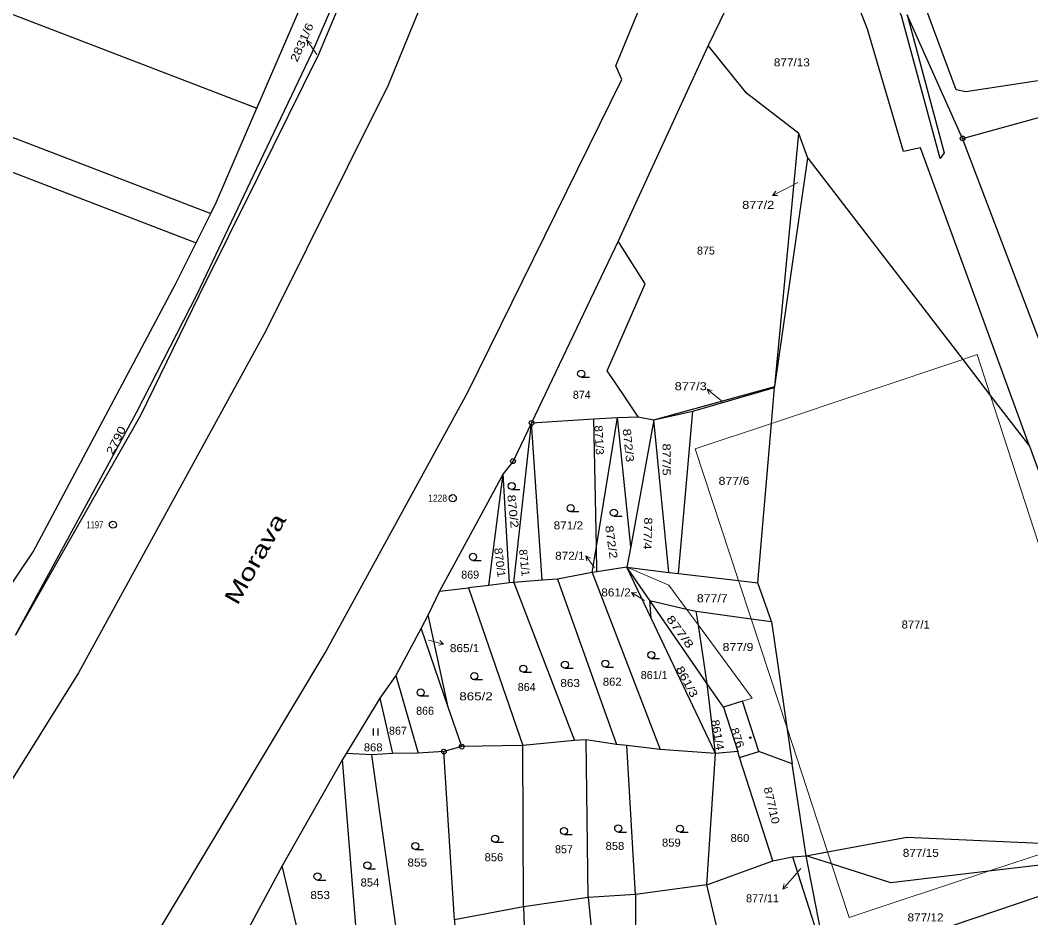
# Model space of a CAD drawing. Extents: x -546984 to -546090, y -1194931 to -1194069.
# Drawn here: x -546479.3 to -546264.7, y -1194458.7 to -1194268.1 of the extents above; entities that cross this region are included whole.
import ezdxf
from ezdxf.enums import TextEntityAlignment as Align

# ---------------------------------------------------------------- set-up
doc = ezdxf.new("R2010")
doc.units = 0
doc.header["$LTSCALE"] = 0.68
for name, color, linetype, lineweight in [('1', 7, 'Continuous', 25), ('3', 7, 'Continuous', 25), ('4', 7, 'Continuous', 13), ('5', 7, 'Continuous', 25), ('7', 7, 'Continuous', 13), ('8', 7, 'Continuous', 25)]:
    doc.layers.add(name, color=color, linetype=linetype, lineweight=lineweight)
doc.layers.add('2', color=7, linetype='Continuous')

msp = doc.modelspace()

# ---------------------------------------------------------------- linework, layer by layer
at = {"layer": '1'}
for p, q in [((-546321.44, -1194249.16), (-546333.19, -1194273.39)), ((-546535.728, -1194271.832), (-546438.82, -1194309.09)), ((-546319.09, -1194345.84), (-546313.93, -1194292.13)), ((-546352.31, -1194314.99), (-546370.72, -1194353.57)), ((-546356.95, -1194379.79), (-546352.43, -1194352.43)), ((-546352.43, -1194352.43), (-546348.07, -1194352.27)), ((-546349.66, -1194379.83), (-546352.43, -1194352.43)), ((-546344.72, -1194352.94), (-546336.5, -1194351.06)), ((-546339.49, -1194385.58), (-546336.5, -1194351.06)), ((-546374.51, -1194387.45), (-546370.72, -1194353.57)), ((-546368.49, -1194387), (-546370.72, -1194353.57)), ((-546264.98, -1194358.54), (-546233.72, -1194444.1)), ((-546379.81, -1194388.1), (-546376.75, -1194364.41)), ((-546375.42, -1194387.56), (-546376.75, -1194364.41)), ((-546356.84, -1194385.21), (-546356.95, -1194379.79)), ((-546345.58, -1194391.31), (-546350.47, -1194384.21)), ((-546357.87, -1194385.37), (-546343.43, -1194422.95)), ((-546341.57, -1194385.33), (-546339.49, -1194385.58)), ((-546390.24, -1194389.34), (-546384.07, -1194388.61)), ((-546384.07, -1194388.61), (-546372.53, -1194422.11)), ((-546319.8, -1194395.78), (-546322.7, -1194387.52)), ((-546390.24, -1194389.34), (-546392.7, -1194394.32)), ((-546345.33, -1194395.05), (-546345.58, -1194391.31)), ((-546392.7, -1194394.32), (-546394.12, -1194397.19)), ((-546388.4, -1194413.93), (-546392.7, -1194394.32)), ((-546399.52, -1194407.25), (-546394.82, -1194423.7)), ((-546329.98, -1194413.96), (-546333.39, -1194409.02)), ((-546402.96, -1194412.02), (-546400.26, -1194423.75)), ((-546361.61, -1194421.01), (-546372.53, -1194422.11)), ((-546352.67, -1194421.88), (-546359.11, -1194420.91)), ((-546372.44, -1194456.33), (-546372.53, -1194422.11)), ((-546326.53, -1194424.65), (-546322.48, -1194423.34)), ((-546410.85, -1194425.09), (-546423.69, -1194447.64)), ((-546410.09, -1194423.81), (-546410.85, -1194425.09)), ((-546407.84, -1194462.95), (-546410.85, -1194425.09)), ((-546387.04, -1194459.12), (-546389.33, -1194423.37)), ((-546333.5, -1194451.68), (-546331.69, -1194423.79)), ((-546326.94, -1194423.37), (-546331.69, -1194423.79)), ((-546423.69, -1194447.64), (-546434.68, -1194468.08)), ((-546419.49, -1194465.08), (-546423.69, -1194447.64))]:
    msp.add_line(p, q, dxfattribs=at)
for points in [[(-546389.24, -1194211.62), (-546383.21, -1194213.85), (-546381.43, -1194214.52), (-546374.55, -1194220.96), (-546389.16, -1194255.29), (-546392.45, -1194260.52), (-546401.16, -1194281.84), (-546427.1, -1194334), (-546466.91, -1194406.62), (-546525.73, -1194500.91), (-546575.37, -1194569.17), (-546611.42, -1194614.13), (-546654.08, -1194661.28), (-546675.45, -1194680.69), (-546700.89, -1194697.8)], [(-546480.28, -1194398.62), (-546454.62, -1194351.38), (-546441.74, -1194326.26), (-546429.78, -1194301.03), (-546417.24, -1194274.74), (-546406, -1194248.75), (-546398.33, -1194228.83), (-546392.14, -1194217.18)], [(-546392.14, -1194217.18), (-546393.03, -1194219.38), (-546404.99, -1194249.12), (-546415.92, -1194275.33), (-546428.91, -1194301.5), (-546441.35, -1194326.56), (-546453.74, -1194351.98), (-546480.28, -1194398.62)], [(-546653.83, -1194720.11), (-546626.66, -1194696.55), (-546572.27, -1194633.02), (-546541.58, -1194595.62), (-546489.43, -1194522.46), (-546452.3, -1194465.52), (-546414.56, -1194402.38), (-546384.23, -1194347.08), (-546351.57, -1194280.62), (-546352.84, -1194277.72), (-546335.99, -1194236.72), (-546326.04, -1194236.79), (-546324.23, -1194237.51), (-546321.88, -1194231.5)], [(-546290.97, -1194266.91), (-546283.11, -1194296.25), (-546283.98, -1194297.43), (-546292.16, -1194267.14), (-546301.17, -1194245.95), (-546309.75, -1194237.15), (-546316.69, -1194232.35)], [(-546223.97, -1194273.81), (-546237.14, -1194276.93), (-546278.51, -1194283.23), (-546280.55, -1194282.82), (-546289.26, -1194259.3), (-546295.56, -1194244.05), (-546298.03, -1194240.43)], [(-546264.98, -1194358.54), (-546288.15, -1194295.14), (-546291.74, -1194295.93), (-546299.4, -1194269.93), (-546306.67, -1194251.25), (-546318.22, -1194242.52)], [(-546518.881, -1194252.193), (-546429.01, -1194286.74), (-546419.67, -1194265.11)], [(-546239.33, -1194397.92), (-546258.87, -1194346.57), (-546279.19, -1194293.17), (-546290.97, -1194266.91)], [(-546537.003, -1194273.318), (-546538.28, -1194278.28), (-546441.91, -1194315.32), (-546438.82, -1194309.09)], [(-546333.19, -1194273.39), (-546333.64, -1194274.33), (-546352.31, -1194314.99)], [(-546313.93, -1194292.13), (-546325.1, -1194283.56), (-546333.19, -1194273.39)], [(-546279.19, -1194293.17), (-546239.15, -1194282.15), (-546214.13, -1194275.26)], [(-546438.82, -1194309.09), (-546437.6, -1194306.64), (-546429.01, -1194286.74)], [(-546319.09, -1194345.84), (-546312.06, -1194297.34), (-546313.93, -1194292.13)], [(-546312.06, -1194297.34), (-546279.16, -1194340.1), (-546273.25, -1194347.79), (-546264.98, -1194358.54)], [(-546566.87, -1194389.76), (-546564.43, -1194388.89), (-546559.37, -1194387.86), (-546556.14, -1194387.71), (-546553.09, -1194388.04), (-546526.4, -1194394.07), (-546501.89, -1194394.85), (-546489.42, -1194394.32), (-546486.31, -1194393.34), (-546483.36, -1194391.08), (-546476.54, -1194380.93), (-546446.29, -1194324.14), (-546441.91, -1194315.32)], [(-546348.07, -1194352.27), (-546350.47, -1194348.7), (-546353.12, -1194344.75), (-546354.63, -1194342.5), (-546346.62, -1194324.07), (-546352.31, -1194314.99)], [(-546348.07, -1194352.27), (-546344.72, -1194352.94), (-546319.09, -1194345.84)], [(-546336.5, -1194351.06), (-546319.15, -1194346.03), (-546319.09, -1194345.84)], [(-546322.7, -1194387.52), (-546319.8, -1194353.68), (-546319.15, -1194346.03)], [(-546370.72, -1194353.57), (-546357.47, -1194352.74), (-546352.43, -1194352.43)], [(-546370.72, -1194353.57), (-546374.65, -1194361.7), (-546376.75, -1194364.41)], [(-546357.87, -1194385.37), (-546356.95, -1194379.79), (-546357.47, -1194352.74)], [(-546376.75, -1194364.41), (-546382.42, -1194374.85), (-546390.24, -1194389.34)], [(-546331.69, -1194423.79), (-546345.33, -1194395.05), (-546350.47, -1194384.21), (-546356.84, -1194385.21), (-546357.87, -1194385.37)], [(-546365.22, -1194386.75), (-546368.49, -1194387), (-546374.51, -1194387.45), (-546361.61, -1194421.01)], [(-546357.87, -1194385.37), (-546365.22, -1194386.75), (-546352.67, -1194421.88)], [(-546339.49, -1194385.58), (-546326.76, -1194387.05), (-546322.7, -1194387.52)], [(-546374.51, -1194387.45), (-546375.42, -1194387.56), (-546379.81, -1194388.1), (-546384.07, -1194388.61)], [(-546331.69, -1194423.79), (-546333.39, -1194409.02), (-546345.58, -1194391.31)], [(-546345.58, -1194391.31), (-546337.83, -1194393.1), (-546335.75, -1194393.58)], [(-546333.39, -1194409.02), (-546335.3, -1194396.53), (-546335.75, -1194393.58)], [(-546335.75, -1194393.58), (-546324.09, -1194395.19), (-546319.8, -1194395.78)], [(-546394.12, -1194397.19), (-546399.52, -1194407.25), (-546402.96, -1194412.02), (-546410.09, -1194423.81)], [(-546385.53, -1194422.33), (-546388.4, -1194413.93), (-546394.12, -1194397.19)], [(-546319.8, -1194395.78), (-546316.54, -1194418.2), (-546315.41, -1194425.96)], [(-546322.48, -1194423.34), (-546325.94, -1194412.65), (-546329.98, -1194413.96), (-546326.94, -1194423.37)], [(-546358.67, -1194454.37), (-546359.11, -1194420.91), (-546361.61, -1194421.01)], [(-546372.53, -1194422.11), (-546385.53, -1194422.33), (-546389.33, -1194423.37)], [(-546348.67, -1194453.74), (-546350.47, -1194422.06), (-546352.67, -1194421.88)], [(-546331.69, -1194423.79), (-546343.43, -1194422.95), (-546350.47, -1194422.06)], [(-546319.48, -1194446.55), (-546315.32, -1194445.7), (-546312.37, -1194445.5), (-546315.41, -1194425.96), (-546322.48, -1194423.34)], [(-546399.41, -1194461.39), (-546404.6, -1194424.09), (-546410.09, -1194423.81)], [(-546389.33, -1194423.37), (-546394.82, -1194423.7), (-546400.26, -1194423.75), (-546404.6, -1194424.09)], [(-546333.5, -1194451.68), (-546319.48, -1194446.55), (-546326.53, -1194424.65), (-546326.94, -1194423.37)], [(-546312.37, -1194445.5), (-546307.85, -1194444.66), (-546291.01, -1194441.53), (-546256.43, -1194443.08), (-546233.72, -1194444.1)], [(-546233.72, -1194444.1), (-546273.66, -1194448.8), (-546294.44, -1194451.24), (-546307.01, -1194447.22), (-546312.37, -1194445.5)], [(-546307.77, -1194469.14), (-546299.75, -1194466.54), (-546235.74, -1194444.89), (-546233.72, -1194444.1)], [(-546315.32, -1194445.7), (-546307.77, -1194469.14), (-546312.37, -1194445.5)], [(-546323.11, -1194495.59), (-546333.5, -1194451.68), (-546348.67, -1194453.74), (-546348.66, -1194493.19)], [(-546358.67, -1194454.37), (-546372.44, -1194456.33), (-546371.21, -1194490.86)], [(-546348.67, -1194453.74), (-546358.67, -1194454.37), (-546354.91, -1194491.78)], [(-546372.44, -1194456.33), (-546387.04, -1194459.12), (-546385.83, -1194490.18)]]:
    msp.add_lwpolyline(points, dxfattribs=at)
msp.add_lwpolyline([(-546350.47, -1194384.21), (-546341.57, -1194385.33), (-546344.72, -1194352.94), (-546349.66, -1194379.83)], close=True, dxfattribs=at)
at = {"layer": '3'}
for p, q in [((-546360.173, -1194343.88), (-546358.423, -1194343.88)), ((-546374.933, -1194367.73), (-546373.183, -1194367.73)), ((-546362.413, -1194372.42), (-546360.663, -1194372.42)), ((-546353.243, -1194373.38), (-546351.493, -1194373.38)), ((-546383.153, -1194382.77), (-546381.403, -1194382.77)), ((-546345.273, -1194403.62), (-546343.523, -1194403.62)), ((-546363.633, -1194405.66), (-546361.883, -1194405.66)), ((-546355.043, -1194405.44), (-546353.293, -1194405.44)), ((-546382.873, -1194408.1), (-546381.123, -1194408.1)), ((-546372.473, -1194406.51), (-546370.723, -1194406.51)), ((-546394.263, -1194411.57), (-546392.513, -1194411.57)), ((-546404.271, -1194419.98), (-546404.271, -1194418.48)), ((-546403.27, -1194419.98), (-546403.27, -1194418.48)), ((-546352.313, -1194440.46), (-546350.563, -1194440.46)), ((-546339.183, -1194440.51), (-546337.433, -1194440.51)), ((-546378.453, -1194442.64), (-546376.703, -1194442.64)), ((-546363.823, -1194440.99), (-546362.073, -1194440.99)), ((-546395.403, -1194444.17), (-546393.653, -1194444.17)), ((-546405.563, -1194448.28), (-546403.813, -1194448.28)), ((-546416.163, -1194450.65), (-546414.413, -1194450.65))]:
    msp.add_line(p, q, dxfattribs=at)
for centre in [(-546360.1729, -1194343.1298), (-546374.9329, -1194366.9798), (-546362.4129, -1194371.6698), (-546353.2429, -1194372.6298), (-546383.1529, -1194382.0198), (-546355.0429, -1194404.6898), (-546345.2729, -1194402.8698), (-546372.4729, -1194405.7598), (-546363.6329, -1194404.9098), (-546382.8729, -1194407.3498), (-546394.2629, -1194410.8198), (-546363.8229, -1194440.2398), (-546352.3129, -1194439.7098), (-546339.1829, -1194439.7598), (-546378.4529, -1194441.8898), (-546395.4029, -1194443.4198), (-546405.5629, -1194447.5298), (-546416.1629, -1194449.8998)]:
    msp.add_circle(centre, 0.75, dxfattribs=at)
at = {"layer": '4'}
for p, q in [((-546335.95, -1194359.07), (-546326.76, -1194387.05)), ((-546350.47, -1194384.21), (-546341.56, -1194388.04)), ((-546323.88, -1194412.02), (-546325.94, -1194412.65)), ((-546307.01, -1194447.22), (-546303.27, -1194458.62)), ((-546303.27, -1194458.62), (-546273.66, -1194448.8))]:
    msp.add_line(p, q, dxfattribs=at)
for points in [[(-546335.95, -1194359.07), (-546319.8, -1194353.68), (-546279.16, -1194340.1), (-546276.08, -1194339.07)], [(-546276.08, -1194339.07), (-546273.25, -1194347.79), (-546243.71, -1194438.86)], [(-546341.56, -1194388.04), (-546337.83, -1194393.1), (-546335.3, -1194396.53), (-546323.88, -1194412.02)], [(-546326.76, -1194387.05), (-546324.09, -1194395.19), (-546316.54, -1194418.2)], [(-546316.54, -1194418.2), (-546307.85, -1194444.66), (-546307.01, -1194447.22)], [(-546273.66, -1194448.8), (-546256.43, -1194443.08), (-546243.71, -1194438.86)]]:
    msp.add_lwpolyline(points, dxfattribs=at)
at = {"layer": '5'}
msp.add_circle((-546324.2668, -1194420.4192), 0.175, dxfattribs=at)
at = {"layer": '7'}
for p, q in [((-546418.371, -1194272.392), (-546418.207, -1194273.499)), ((-546319.534, -1194305.272), (-546318.414, -1194305.264)), ((-546333.442, -1194346.421), (-546332.979, -1194347.441)), ((-546359.174, -1194381.772), (-546358.99, -1194382.877)), ((-546349.475, -1194389.57), (-546348.891, -1194390.525)), ((-546389.381, -1194400.557), (-546390.219, -1194399.814)), ((-546317.329, -1194452.565), (-546316.294, -1194452.138))]:
    msp.add_line(p, q, dxfattribs=at)
for points in [[(-546416.32, -1194275.32), (-546416.65, -1194274.85), (-546418.371, -1194272.392), (-546417.387, -1194272.925)], [(-546314.19, -1194302.53), (-546316.86, -1194303.91), (-546319.534, -1194305.272), (-546318.869, -1194304.372)], [(-546330.2, -1194349.04), (-546331.11, -1194348.31), (-546333.442, -1194346.421), (-546332.349, -1194346.663)], [(-546357.35, -1194384.28), (-546357.41, -1194384.2), (-546359.174, -1194381.772), (-546358.18, -1194382.288)], [(-546346.72, -1194391.29), (-546346.93, -1194391.16), (-546349.475, -1194389.57), (-546348.36, -1194389.676)], [(-546392.56, -1194399.7), (-546392.28, -1194399.78), (-546389.381, -1194400.557), (-546390.478, -1194400.781)], [(-546313.55, -1194448.24), (-546315.36, -1194450.3), (-546317.329, -1194452.565), (-546317.05, -1194451.481)]]:
    msp.add_lwpolyline(points, dxfattribs=at)
at = {"layer": '8'}
for centre, radius in [((-546279.19, -1194293.1699), 0.5), ((-546279.19, -1194293.1699), 0.0303), ((-546370.72, -1194353.5699), 0.5), ((-546370.72, -1194353.5699), 0.0303), ((-546374.65, -1194361.6999), 0.5), ((-546374.65, -1194361.6999), 0.0303), ((-546387.44, -1194369.5598), 0.75), ((-546387.44, -1194369.5598), 0.03), ((-546459.61, -1194375.1998), 0.75), ((-546459.61, -1194375.1998), 0.03), ((-546389.33, -1194423.3699), 0.5), ((-546389.33, -1194423.3699), 0.0303), ((-546385.53, -1194422.3299), 0.5), ((-546385.53, -1194422.3299), 0.0303)]:
    msp.add_circle(centre, radius, dxfattribs=at)

# ---------------------------------------------------------------- texts
at = {"layer": '2', "width": 1.25}
msp.add_text('2831/6', height=1.7, rotation=66, dxfattribs=at).set_placement((-546416.9415, -1194269.1255), align=Align.RIGHT)
at = {"layer": '2'}
for s, width, p in [('877/13', 1.1, (-546319.27, -1194277.852)), ('877/6', 1.15, (-546331, -1194366.73)), ('871/2', 1.1, (-546366.02, -1194376.19)), ('877/7', 1.15, (-546335.61, -1194391.66)), ('877/1', 1.05, (-546292.14, -1194397.24)), ('865/1', 1.1, (-546388.052, -1194402.255)), ('877/9', 1.15, (-546330.15, -1194402.02)), ('863', 1.1, (-546364.61, -1194409.67)), ('862', 1.05, (-546355.57, -1194409.38)), ('865/2', 1.25, (-546386.06, -1194412.49)), ('858', 1.05, (-546355, -1194444.26)), ('860', 1.05, (-546328.46, -1194442.57)), ('877/15', 1.1, (-546291.89, -1194445.73)), ('856', 1.05, (-546380.69, -1194446.67)), ('854', 1.05, (-546407.02, -1194452.03)), ('877/12', 1.1, (-546290.88, -1194459.44))]:
    msp.add_text(s, height=1.7, dxfattribs=dict(at, width=width)).set_placement(p)
for s, width, p in [('877/2', 1.2, (-546319.17, -1194308.123)), ('877/3', 1.2, (-546333.499, -1194346.635)), ('872/1', 1.1, (-546359.446, -1194382.63)), ('861/2', 1.1, (-546349.646, -1194390.42))]:
    msp.add_text(s, height=1.7, dxfattribs=dict(at, width=width)).set_placement(p, align=Align.RIGHT)
for s, p in [('875', (-546333.6965, -1194317.83)), ('866', (-546393.3335, -1194415.56)), ('867', (-546399.0835, -1194419.78))]:
    msp.add_text(s, height=1.7, dxfattribs=at).set_placement(p, align=Align.CENTER)
for s, p in [('874', (-546361.94, -1194348.45)), ('869', (-546385.64, -1194386.65)), ('861/1', (-546347.52, -1194407.97)), ('864', (-546373.64, -1194410.51)), ('857', (-546365.73, -1194444.97))]:
    msp.add_text(s, height=1.7, dxfattribs=at).set_placement(p)
for s, rotation, width, p in [('2790', 63, 1.25, (-546459.622, -1194360.465)), ('871/3', 273, 1.1, (-546357.358, -1194354.144)), ('872/3', 276, 1.25, (-546351.355, -1194354.888)), ('877/5', 270, 1.2, (-546342.89, -1194357.95)), ('870/2', 276, 1.25, (-546375.856, -1194368.898)), ('877/4', 268, 1.2, (-546346.759, -1194373.61)), ('872/2', 278, 1.25, (-546355.091, -1194375.468)), ('870/1', 277, 1.1, (-546378.651, -1194380.211)), ('877/8', 306, 1.4, (-546342.207, -1194395.199)), ('861/3', 298, 1.25, (-546340.12, -1194405.789)), ('861/4', 280, 1.15, (-546332.587, -1194416.747)), ('877/10', 283, 1.15, (-546321.438, -1194431.101))]:
    msp.add_text(s, height=1.7, rotation=rotation, dxfattribs=dict(at, width=width)).set_placement(p)
msp.add_text('871/1', height=1.7, rotation=276, dxfattribs=at).set_placement((-546373.375, -1194380.518))
at = {"layer": '2', "width": 1.15}
msp.add_text('876', height=1.7, rotation=289, dxfattribs=at).set_placement((-546327.7989, -1194420.7208), align=Align.CENTER)
at = {"layer": '2'}
for s, width, p in [('868', 1.05, (-546404.333, -1194423.32)), ('859', 1.05, (-546341.0265, -1194443.56)), ('855', 1.1, (-546394.9795, -1194447.79)), ('853', 1.1, (-546415.5995, -1194454.69))]:
    msp.add_text(s, height=1.7, dxfattribs=dict(at, width=width)).set_placement(p, align=Align.CENTER)
msp.add_text('877/11', height=1.7, dxfattribs=at).set_placement((-546318.206, -1194455.383), align=Align.RIGHT)
at = {"layer": '7', "width": 1.4}
msp.add_text('Morava', height=3.4, rotation=60.367, dxfattribs=at).set_placement((-546433.175, -1194392.481))
at = {"layer": '8'}
for s, width, p in [('1228', 0.9, (-546388.65, -1194370.31)), ('1197', 0.7, (-546461.658, -1194375.95))]:
    msp.add_text(s, height=1.5, dxfattribs=dict(at, width=width)).set_placement(p, align=Align.RIGHT)

doc.saveas('drawing.dxf')
